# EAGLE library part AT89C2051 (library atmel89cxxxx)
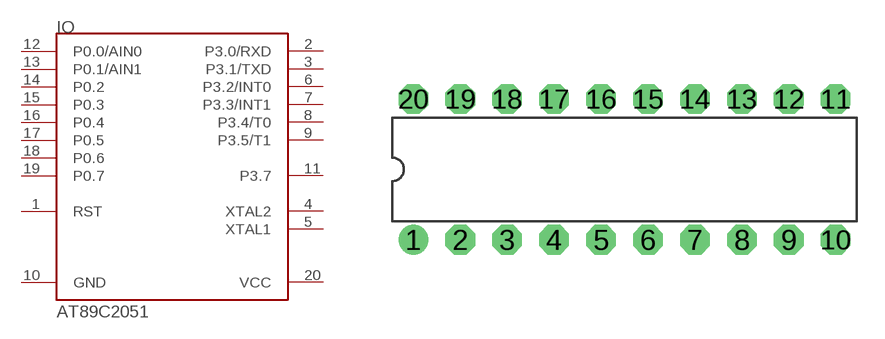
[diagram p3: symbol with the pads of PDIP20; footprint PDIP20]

Designator prefix IO

## AT89C2051  [PDIP20]
1  RST  pwr
2  P3.0/RXD
3  P3.1/TXD
4  XTAL2  pwr
5  XTAL1  pwr
6  P3.2/INT0
7  P3.3/INT1
8  P3.4/T0
9  P3.5/T1
10  GND  pwr
11  P3.7
12  P0.0/AIN0
13  P0.1/AIN1
14  P0.2
15  P0.3
16  P0.4
17  P0.5
18  P0.6
19  P0.7
20  VCC  pwr

## Footprint PDIP20 (pad centres in mm)
drill 0.813 pad 1.6 round: 1 -11.43,-3.81
drill 0.813 pad 1.6 octagon: 2 -8.89,-3.81; 3 -6.35,-3.81; 4 -3.81,-3.81; 5 -1.27,-3.81; 6 1.27,-3.81; 7 3.81,-3.81; 8 6.35,-3.81; 9 8.89,-3.81; 10 11.43,-3.81; 11 11.43,3.81; 12 8.89,3.81; 13 6.35,3.81; 14 3.81,3.81; 15 1.27,3.81; 16 -1.27,3.81; 17 -3.81,3.81; 18 -6.35,3.81; 19 -8.89,3.81; 20 -11.43,3.81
